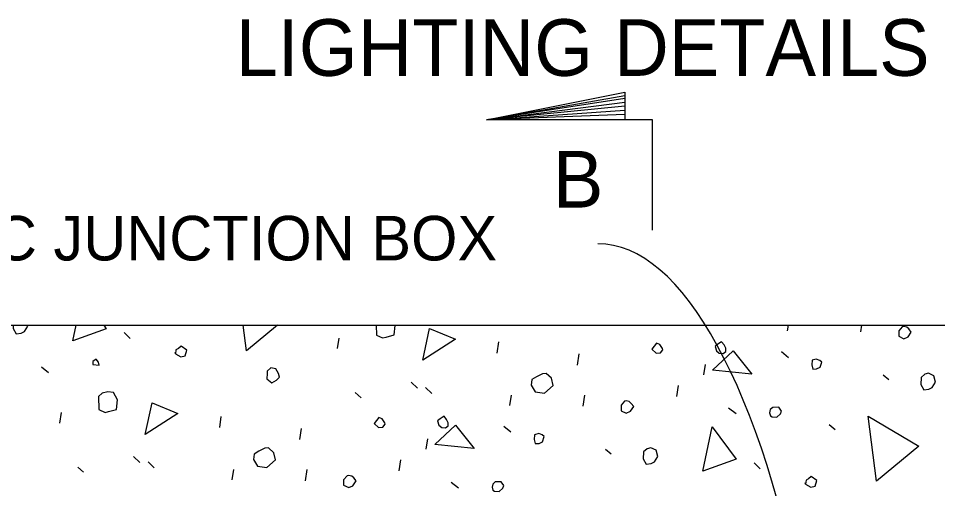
# Model space of a CAD drawing. Extents: x -1660015.2 to -1659984.9, y 2580594.2 to 2580616.7.
# Drawn here: x -1660013.123 to -1660010.005, y 2580603.502 to 2580605.097 of the extents above; entities that cross this region are included whole.
import ezdxf

# ---------------------------------------------------------------- set-up
doc = ezdxf.new("R2010")
doc.units = 0
for name, color, linetype in [('Miscellaneous', 7, 'Continuous'), ('Miscellaneous3', 7, 'Continuous'), ('PlotBorder_dp', 7, 'Continuous'), ('SheetLines_dp', 7, 'Continuous')]:
    doc.layers.add(name, color=color, linetype=linetype)

msp = doc.modelspace()

# ---------------------------------------------------------------- linework, layer by layer
at = {"layer": 'Miscellaneous'}
for p, q in [((-1660012.765, 2580604.0316), (-1660012.7441, 2580604.0113)), ((-1660010.5147, 2580604.0367), (-1660010.5114, 2580604.0559)), ((-1660010.2654, 2580604.0336), (-1660010.2622, 2580604.0559)), ((-1660012.0413, 2580603.9771), (-1660012.0352, 2580604.0124)), ((-1660011.4989, 2580603.9619), (-1660011.4934, 2580603.9996)), ((-1660010.5347, 2580603.9666), (-1660010.5114, 2580603.947)), ((-1660011.2265, 2580603.921), (-1660011.2211, 2580603.9587)), ((-1660013.0445, 2580603.9153), (-1660013.0211, 2580603.8957)), ((-1660010.7984, 2580603.8882), (-1660010.7923, 2580603.9235)), ((-1660010.1902, 2580603.8881), (-1660010.1705, 2580603.8727)), ((-1660011.7907, 2580603.863), (-1660011.7698, 2580603.8428)), ((-1660011.7419, 2580603.8451), (-1660011.7209, 2580603.8248)), ((-1660010.89, 2580603.8145), (-1660010.8845, 2580603.8522)), ((-1660011.9805, 2580603.8277), (-1660011.9602, 2580603.8099)), ((-1660011.4565, 2580603.7844), (-1660011.4504, 2580603.8196)), ((-1660011.2072, 2580603.7813), (-1660011.2017, 2580603.819)), ((-1660010.7141, 2580603.7762), (-1660010.6883, 2580603.7573)), ((-1660012.983, 2580603.7247), (-1660012.977, 2580603.76)), ((-1660012.4406, 2580603.7096), (-1660012.4352, 2580603.7473)), ((-1660011.4765, 2580603.7143), (-1660011.4531, 2580603.6947)), ((-1660010.3729, 2580603.7201), (-1660010.3526, 2580603.7023)), ((-1660012.1683, 2580603.6687), (-1660012.1629, 2580603.7064)), ((-1660011.7402, 2580603.6359), (-1660011.7341, 2580603.6712)), ((-1660011.132, 2580603.6358), (-1660011.1123, 2580603.6204)), ((-1660012.7325, 2580603.6107), (-1660012.7115, 2580603.5904)), ((-1660012.6837, 2580603.5927), (-1660012.6627, 2580603.5724)), ((-1660011.8317, 2580603.5622), (-1660011.8263, 2580603.5999)), ((-1660010.6278, 2580603.5897), (-1660010.6069, 2580603.5694)), ((-1660012.9223, 2580603.5754), (-1660012.902, 2580603.5575)), ((-1660012.3982, 2580603.532), (-1660012.3922, 2580603.5673)), ((-1660012.1489, 2580603.5289), (-1660012.1435, 2580603.5666)), ((-1660011.6558, 2580603.5239), (-1660011.6301, 2580603.5049))]:
    msp.add_line(p, q, dxfattribs=at)
for points in [[(-1660013.1406, 2580604.0559), (-1660013.1412, 2580604.0447), (-1660013.1312, 2580604.0267), (-1660013.1137, 2580604.0288), (-1660013.1023, 2580604.0344), (-1660013.0917, 2580604.0528), (-1660013.0925, 2580604.0559)], [(-1660012.9386, 2580604.0032), (-1660012.9274, 2580604.0559)], [(-1660012.8341, 2580604.0559), (-1660012.8253, 2580604.0439), (-1660012.9386, 2580604.0032)], [(-1660012.3498, 2580603.9695), (-1660012.3608, 2580604.0559)], [(-1660012.2449, 2580604.0559), (-1660012.3498, 2580603.9695)], [(-1660011.9096, 2580604.0559), (-1660011.9086, 2580604.023), (-1660011.8878, 2580604.013), (-1660011.8758, 2580604.0162), (-1660011.8492, 2580604.0234), (-1660011.8449, 2580604.0556), (-1660011.8451, 2580604.0559)], [(-1660011.7514, 2580603.9383), (-1660011.7283, 2580604.0454), (-1660011.641, 2580604.0093), (-1660011.7514, 2580603.9383)], [(-1660010.1369, 2580604.037), (-1660010.1372, 2580604.0188), (-1660010.1195, 2580604.0106), (-1660010.1056, 2580604.0169), (-1660010.0944, 2580604.0329), (-1660010.1024, 2580604.0437), (-1660010.1092, 2580604.0496), (-1660010.1202, 2580604.0518), (-1660010.125, 2580604.0506), (-1660010.1369, 2580604.037)], [(-1660010.9745, 2580603.9756), (-1660010.9604, 2580603.9613), (-1660010.9452, 2580603.9628), (-1660010.9375, 2580603.9726), (-1660010.9388, 2580603.9774), (-1660010.9475, 2580603.9906), (-1660010.9591, 2580603.9953), (-1660010.9668, 2580603.9855), (-1660010.9745, 2580603.9756)], [(-1660010.7555, 2580603.9696), (-1660010.7457, 2580603.9619), (-1660010.7323, 2580603.9603), (-1660010.724, 2580603.9677), (-1660010.7241, 2580603.978), (-1660010.7298, 2580603.9894), (-1660010.7378, 2580604.0002), (-1660010.751, 2580603.9915), (-1660010.7594, 2580603.9841), (-1660010.7555, 2580603.9696)], [(-1660012.5904, 2580603.9594), (-1660012.572, 2580603.9487), (-1660012.5575, 2580603.9526), (-1660012.5524, 2580603.9721), (-1660012.5714, 2580603.9851), (-1660012.5798, 2580603.9777), (-1660012.5888, 2580603.9727), (-1660012.5904, 2580603.9594), (-1660012.5917, 2580603.9642)], [(-1660010.769, 2580603.9039), (-1660010.6985, 2580603.9693), (-1660010.6359, 2580603.8904), (-1660010.769, 2580603.9039)], [(-1660012.8706, 2580603.9231), (-1660012.8493, 2580603.921), (-1660012.8519, 2580603.9307), (-1660012.8599, 2580603.9415), (-1660012.8707, 2580603.9334), (-1660012.8706, 2580603.9231)], [(-1660010.4321, 2580603.9217), (-1660010.4282, 2580603.9072), (-1660010.4155, 2580603.908), (-1660010.4041, 2580603.9137), (-1660010.3983, 2580603.9307), (-1660010.4051, 2580603.9367), (-1660010.4167, 2580603.9413), (-1660010.4311, 2580603.9375), (-1660010.4321, 2580603.9217)], [(-1660012.28, 2580603.8924), (-1660012.2803, 2580603.8742), (-1660012.2637, 2580603.8605), (-1660012.2481, 2580603.8699), (-1660012.2379, 2580603.8804), (-1660012.2412, 2580603.8925), (-1660012.2505, 2580603.9081), (-1660012.267, 2580603.9114), (-1660012.2795, 2580603.9003), (-1660012.28, 2580603.8924)], [(-1660011.3842, 2580603.8529), (-1660011.3705, 2580603.8307), (-1660011.3383, 2580603.8264), (-1660011.309, 2580603.8523), (-1660011.3155, 2580603.8765), (-1660011.3328, 2580603.8926), (-1660011.3455, 2580603.8918), (-1660011.3659, 2580603.8811), (-1660011.3815, 2580603.8717), (-1660011.3842, 2580603.8529)], [(-1660010.0609, 2580603.8788), (-1660010.0623, 2580603.8551), (-1660010.0523, 2580603.8371), (-1660010.0347, 2580603.8392), (-1660010.0233, 2580603.8449), (-1660010.0127, 2580603.8632), (-1660010.0185, 2580603.885), (-1660010.0362, 2580603.8932), (-1660010.0483, 2580603.8899), (-1660010.0609, 2580603.8788)], [(-1660012.8517, 2580603.8143), (-1660012.8504, 2580603.7706), (-1660012.8296, 2580603.7607), (-1660012.8175, 2580603.7639), (-1660012.791, 2580603.771), (-1660012.7867, 2580603.8032), (-1660012.801, 2580603.8279), (-1660012.8199, 2580603.8306), (-1660012.8392, 2580603.8254), (-1660012.8517, 2580603.8143)], [(-1660012.6931, 2580603.6859), (-1660012.6701, 2580603.7931), (-1660012.5827, 2580603.7569), (-1660012.6931, 2580603.6859)], [(-1660011.0787, 2580603.7847), (-1660011.079, 2580603.7665), (-1660011.0612, 2580603.7583), (-1660011.0474, 2580603.7646), (-1660011.0361, 2580603.7805), (-1660011.0442, 2580603.7913), (-1660011.051, 2580603.7973), (-1660011.0619, 2580603.7995), (-1660011.0668, 2580603.7982), (-1660011.0787, 2580603.7847)], [(-1660010.5723, 2580603.7495), (-1660010.5662, 2580603.746), (-1660010.5504, 2580603.745), (-1660010.5379, 2580603.7562), (-1660010.535, 2580603.7647), (-1660010.5437, 2580603.7779), (-1660010.5643, 2580603.7775), (-1660010.5727, 2580603.7701), (-1660010.5749, 2580603.7592), (-1660010.5723, 2580603.7495)], [(-1660011.6973, 2580603.7173), (-1660011.6875, 2580603.7095), (-1660011.6741, 2580603.7079), (-1660011.6657, 2580603.7154), (-1660011.6659, 2580603.7257), (-1660011.6716, 2580603.7371), (-1660011.6796, 2580603.7479), (-1660011.6928, 2580603.7392), (-1660011.7012, 2580603.7317), (-1660011.6973, 2580603.7173)], [(-1660010.2126, 2580603.5276), (-1660010.2406, 2580603.7478), (-1660010.0685, 2580603.6464), (-1660010.2126, 2580603.5276)], [(-1660011.9163, 2580603.7233), (-1660011.9021, 2580603.709), (-1660011.887, 2580603.7104), (-1660011.8793, 2580603.7203), (-1660011.8806, 2580603.7251), (-1660011.8893, 2580603.7383), (-1660011.9009, 2580603.7429), (-1660011.9086, 2580603.7331), (-1660011.9163, 2580603.7233)], [(-1660011.7107, 2580603.6515), (-1660011.6403, 2580603.717), (-1660011.5777, 2580603.638), (-1660011.7107, 2580603.6515)], [(-1660011.3739, 2580603.6693), (-1660011.37, 2580603.6548), (-1660011.3573, 2580603.6557), (-1660011.3458, 2580603.6613), (-1660011.3401, 2580603.6784), (-1660011.3468, 2580603.6843), (-1660011.3584, 2580603.689), (-1660011.3729, 2580603.6851), (-1660011.3739, 2580603.6693)], [(-1660010.8014, 2580603.5613), (-1660010.7694, 2580603.7122), (-1660010.6881, 2580603.602), (-1660010.8014, 2580603.5613)], [(-1660012.326, 2580603.6006), (-1660012.3123, 2580603.5783), (-1660012.2801, 2580603.574), (-1660012.2508, 2580603.6), (-1660012.2573, 2580603.6241), (-1660012.2745, 2580603.6402), (-1660012.2873, 2580603.6394), (-1660012.3077, 2580603.6288), (-1660012.3233, 2580603.6194), (-1660012.326, 2580603.6006)], [(-1660011.0026, 2580603.6265), (-1660011.004, 2580603.6028), (-1660010.994, 2580603.5848), (-1660010.9765, 2580603.5869), (-1660010.9651, 2580603.5925), (-1660010.9545, 2580603.6109), (-1660010.9603, 2580603.6326), (-1660010.978, 2580603.6408), (-1660010.9901, 2580603.6376), (-1660011.0026, 2580603.6265)], [(-1660012.0204, 2580603.5323), (-1660012.0207, 2580603.5141), (-1660012.003, 2580603.5059), (-1660011.9892, 2580603.5122), (-1660011.9779, 2580603.5282), (-1660011.986, 2580603.539), (-1660011.9928, 2580603.5449), (-1660012.0037, 2580603.5472), (-1660012.0085, 2580603.5459), (-1660012.0204, 2580603.5323)], [(-1660010.4532, 2580603.5174), (-1660010.4348, 2580603.5068), (-1660010.4203, 2580603.5107), (-1660010.4152, 2580603.5302), (-1660010.4342, 2580603.5432), (-1660010.4426, 2580603.5358), (-1660010.4516, 2580603.5308), (-1660010.4532, 2580603.5174), (-1660010.4545, 2580603.5223)], [(-1660011.5141, 2580603.4972), (-1660011.508, 2580603.4936), (-1660011.4922, 2580603.4927), (-1660011.4796, 2580603.5038), (-1660011.4768, 2580603.5124), (-1660011.4855, 2580603.5255), (-1660011.5061, 2580603.5252), (-1660011.5144, 2580603.5178), (-1660011.5167, 2580603.5068), (-1660011.5141, 2580603.4972)]]:
    msp.add_lwpolyline(points, dxfattribs=at)
at = {"layer": 'Miscellaneous3'}
msp.add_line((-1660015.0462, 2580604.0559), (-1660006.558, 2580604.056), dxfattribs=at)
at = {"layer": 'SheetLines_dp'}
for p, q in [((-1660011.5352, 2580604.753), (-1660011.0665, 2580604.8355)), ((-1660011.0665, 2580604.8255), (-1660011.5352, 2580604.753)), ((-1660011.5352, 2580604.753), (-1660011.0665, 2580604.813)), ((-1660011.0665, 2580604.7992), (-1660011.5352, 2580604.753)), ((-1660011.5352, 2580604.753), (-1660011.0665, 2580604.7855)), ((-1660011.0665, 2580604.7705), (-1660011.5352, 2580604.753))]:
    msp.add_line(p, q, dxfattribs=at)
msp.add_lwpolyline([(-1660010.9728, 2580604.378), (-1660010.9728, 2580604.753), (-1660011.5352, 2580604.753), (-1660011.0665, 2580604.8467), (-1660011.0665, 2580604.753)], dxfattribs=at)
msp.add_ellipse((-1660011.1248, 2580601.8147), major_axis=(0.0332, -2.5173), ratio=0.313255, start_param=2.075166, end_param=3.141607, dxfattribs=at)

# ---------------------------------------------------------------- texts
at = {"layer": 'PlotBorder_dp'}
for s, height, p in [('LIGHTING DETAILS FOR CONCRETE BOX GIRDER BRIDGE', 0.192, (-1660012.3863, 2580604.9018)), ('B', 0.192, (-1660011.3101, 2580604.4552)), ('NONMETALLIC JUNCTION BOX', 0.1512, (-1660014.4987, 2580604.2758))]:
    msp.add_text(s, height=height, dxfattribs=at).set_placement(p)

doc.saveas('drawing.dxf')
